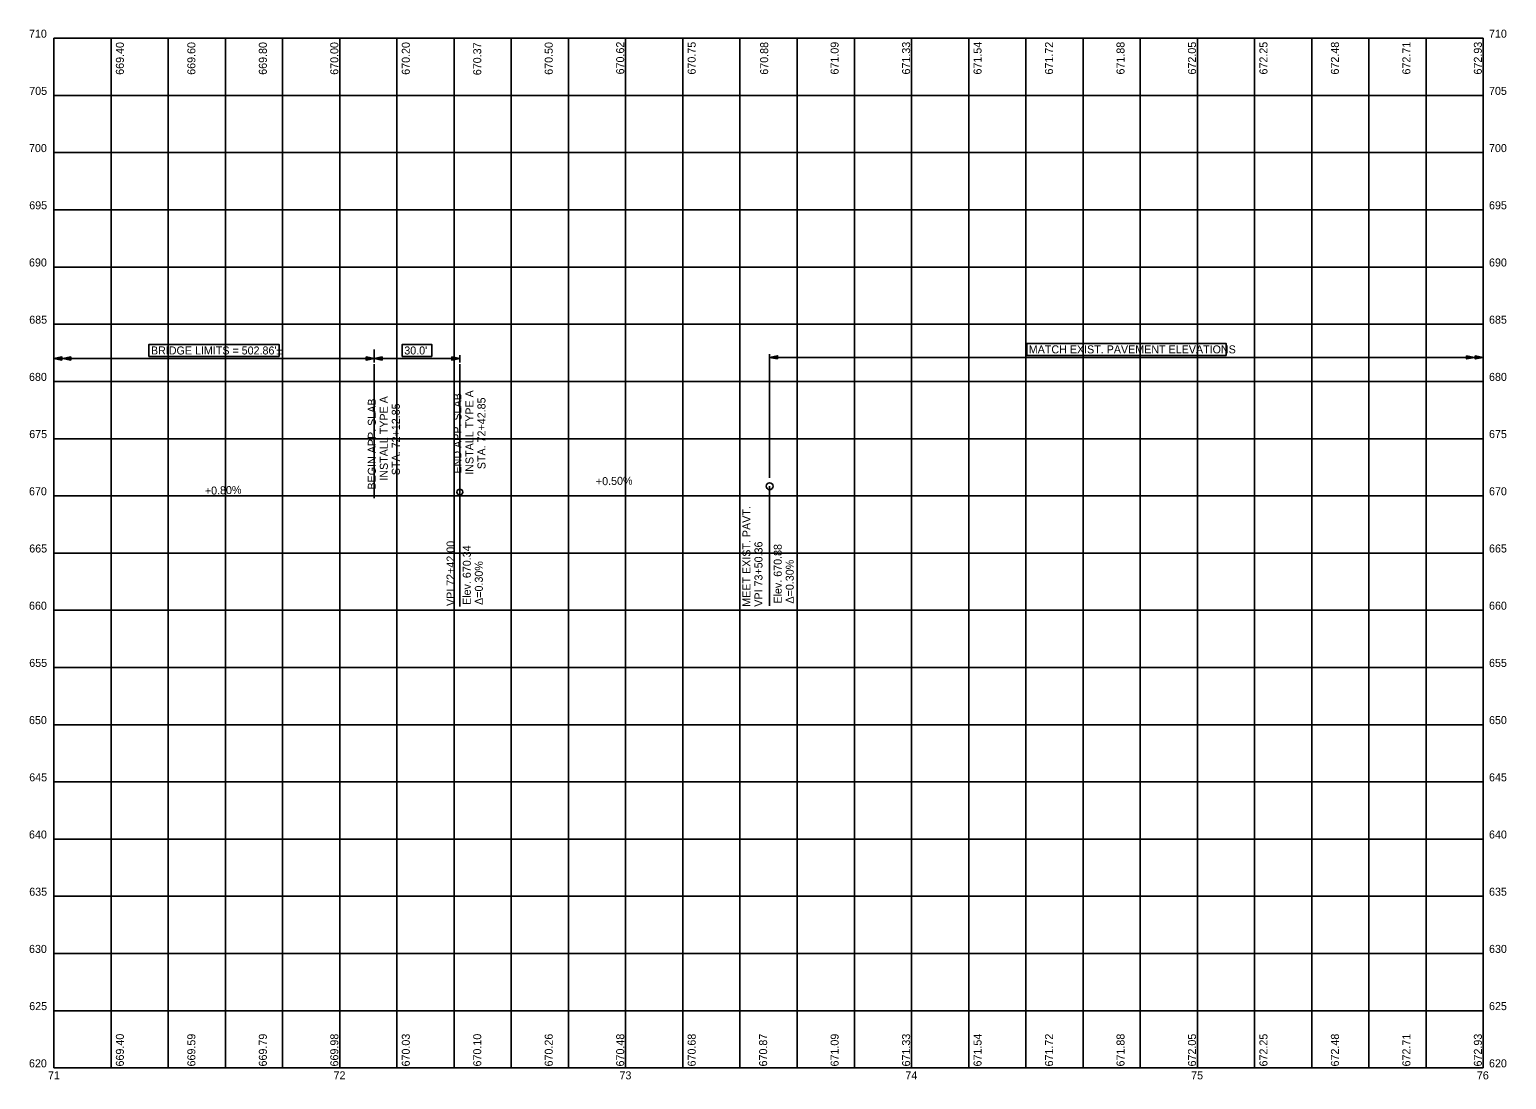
# Model space of a CAD drawing. Extents: x 1498 to 2015, y 616 to 983.
import ezdxf

# ---------------------------------------------------------------- set-up
doc = ezdxf.new("R2010")
doc.units = 0
for name, color, linetype in [('PF_P_Sta_Elev_Text', 7, 'Continuous'), ('PF_P_Text', 7, 'Continuous'), ('PF_P_Text_Strip_Grades_20', 7, 'Continuous'), ('PF_X_Text_Strip_Grade', 7, 'Continuous'), ('SH_Major_Grid_Line', 7, 'Continuous'), ('SH_Text', 7, 'Continuous')]:
    doc.layers.add(name, color=color, linetype=linetype)

msp = doc.modelspace()

# ---------------------------------------------------------------- linework, layer by layer
at = {"layer": 'PF_P_Text'}
for p, q in [((1757.33, 823.38), (1757.33, 781.5)), ((1648.97, 821.34), (1648.97, 781.33))]:
    msp.add_line(p, q, dxfattribs=at)
for centre, radius in [((1648.97, 821.34), 1.02), ((1757.33, 823.38), 1.2)]:
    msp.add_circle(centre, radius, dxfattribs=at)
at = {"layer": 'SH_Major_Grid_Line'}
for p, q in [((1506.97, 980), (2006.97, 980)), ((1506.97, 620), (1506.97, 980)), ((1506.97, 620), (1506.97, 980)), ((1526.97, 620), (1526.97, 980)), ((1546.97, 620), (1546.97, 980)), ((1566.97, 620), (1566.97, 980)), ((1586.97, 620), (1586.97, 980)), ((1606.97, 620), (1606.97, 980)), ((1626.97, 620), (1626.97, 980)), ((1646.97, 620), (1646.97, 980)), ((1666.97, 620), (1666.97, 980)), ((1686.97, 620), (1686.97, 980)), ((1706.97, 620), (1706.97, 980)), ((1726.97, 620), (1726.97, 980)), ((1746.97, 620), (1746.97, 980)), ((1766.97, 620), (1766.97, 980)), ((1786.97, 620), (1786.97, 980)), ((1806.97, 620), (1806.97, 980)), ((1826.97, 620), (1826.97, 980)), ((1846.97, 620), (1846.97, 980)), ((1866.97, 620), (1866.97, 980)), ((1886.97, 620), (1886.97, 980)), ((1906.97, 620), (1906.97, 980)), ((1926.97, 620), (1926.97, 980)), ((1946.97, 620), (1946.97, 980)), ((1966.97, 620), (1966.97, 980)), ((1986.97, 620), (1986.97, 980)), ((2006.97, 620), (2006.97, 980)), ((1506.97, 960), (2006.97, 960)), ((1506.97, 940), (2006.97, 940)), ((1506.97, 920), (2006.97, 920)), ((1506.97, 900), (2006.97, 900)), ((1506.97, 880), (2006.97, 880)), ((1506.97, 860), (2006.97, 860)), ((1506.97, 840), (2006.97, 840)), ((1506.97, 820), (2006.97, 820)), ((1506.97, 800), (2006.97, 800)), ((1506.97, 780), (2006.97, 780)), ((1506.97, 760), (2006.97, 760)), ((1506.97, 740), (2006.97, 740)), ((1506.97, 720), (2006.97, 720)), ((1506.97, 700), (2006.97, 700)), ((1506.97, 680), (2006.97, 680)), ((1506.97, 660), (2006.97, 660)), ((1506.97, 640), (2006.97, 640)), ((1506.97, 620), (2006.97, 620))]:
    msp.add_line(p, q, dxfattribs=at)
at = {"layer": 'SH_Text'}
for p, q in [((1506.97, 871.13), (1506.97, 866.64)), ((1619.01, 868.04), (1506.97, 868.04)), ((1619.01, 871.13), (1619.01, 866.64)), ((1619.01, 871.13), (1619.01, 866.64)), ((1619.01, 868.04), (1648.97, 868.04)), ((1648.97, 869.17), (1648.97, 866.64)), ((1757.33, 869.53), (1757.33, 826.32)), ((1757.33, 868.42), (2006.97, 868.42)), ((2006.97, 869.53), (2006.97, 867.02)), ((1619.01, 819.17), (1619.01, 866.08)), ((1648.97, 821.24), (1648.97, 866.1))]:
    msp.add_line(p, q, dxfattribs=at)
for points in [[(1847.29, 869.12), (1917.01, 869.12), (1917.01, 873.32), (1847.29, 873.32)], [(1509.77, 867.48), (1506.97, 868.04), (1509.77, 868.6)], [(1512.89, 867.48), (1510.09, 868.04), (1512.89, 868.6)], [(1540.24, 868.74), (1585.74, 868.74), (1585.74, 872.94), (1540.24, 872.94)], [(1616.21, 868.6), (1619.01, 868.04), (1616.21, 867.48)], [(1621.81, 867.48), (1619.01, 868.04), (1621.81, 868.6)], [(1628.85, 868.74), (1639.13, 868.74), (1639.13, 872.94), (1628.85, 872.94)], [(1646.17, 868.6), (1648.97, 868.04), (1646.17, 867.48)], [(1760.13, 867.86), (1757.33, 868.42), (1760.13, 868.98)], [(2001.1, 868.98), (2003.9, 868.42), (2001.1, 867.86)], [(2004.17, 868.98), (2006.97, 868.42), (2004.17, 867.86)]]:
    msp.add_lwpolyline(points, close=True, dxfattribs=at)

# ---------------------------------------------------------------- texts
at = {"layer": 'PF_P_Sta_Elev_Text'}
for s, p in [('710', (1498.28, 980.2)), ('710', (2008.97, 980.2)), ('705', (1498.36, 960.2)), ('705', (2008.97, 960.2)), ('700', (1498.28, 940.2)), ('700', (2008.97, 940.2)), ('695', (1498.36, 920.2)), ('695', (2008.97, 920.2)), ('690', (1498.28, 900.2)), ('690', (2008.97, 900.2)), ('685', (1498.36, 880.2)), ('685', (2008.97, 880.2)), ('680', (1498.28, 860.2)), ('680', (2008.97, 860.2)), ('675', (1498.36, 840.2)), ('675', (2008.97, 840.2)), ('670', (1498.28, 820.2)), ('670', (2008.97, 820.2)), ('665', (1498.36, 800.2)), ('665', (2008.97, 800.2)), ('660', (1498.28, 780.2)), ('660', (2008.97, 780.2)), ('655', (1498.36, 760.2)), ('655', (2008.97, 760.2)), ('650', (1498.28, 740.2)), ('650', (2008.97, 740.2)), ('645', (1498.36, 720.2)), ('645', (2008.97, 720.2)), ('640', (1498.28, 700.2)), ('640', (2008.97, 700.2)), ('635', (1498.36, 680.2)), ('635', (2008.97, 680.2)), ('630', (1498.28, 660.2)), ('630', (2008.97, 660.2)), ('625', (1498.36, 640.2)), ('625', (2008.97, 640.2)), ('620', (1498.28, 620.2)), ('620', (2008.97, 620.2)), ('71', (1504.94, 616)), ('72', (1604.81, 616)), ('73', (1704.82, 616)), ('74', (1804.82, 616)), ('75', (1904.78, 616)), ('76', (2004.73, 616))]:
    msp.add_text(s, height=2.8, dxfattribs=at).set_placement(p)
at = {"layer": 'PF_P_Text'}
for s, rotation, p in [('BEGIN APP. SLAB', 90, (1619.59, 822.21)), ('INSTALL TYPE A', 90, (1623.79, 825.31)), ('END APP. SLAB', 90, (1649.55, 827.81)), ('INSTALL TYPE A', 90, (1653.75, 827.38)), ('STA. 72+42.85', 90, (1657.95, 829.32)), ('STA. 72+12.85', 90, (1627.99, 827.25)), ('+0.50%', 1.1444, (1696.6, 823.69)), ('+0.80%', 1.8328, (1559.84, 820.36)), ('MEET EXIST. PAVT.', 90, (1750.64, 781.24)), ('VPI 72+42.00', 90, (1647.13, 781.48)), ('Elev. 670.34', 90, (1652.82, 781.87)), ('VPI 73+50.36', 90, (1754.84, 781.24)), ('Elev. 670.88', 90, (1761.57, 782.35)), ('Δ=0.30%', 90, (1657.02, 781.87)), ('Δ=0.30%', 90, (1765.77, 782.35))]:
    msp.add_text(s, height=2.8, rotation=rotation, dxfattribs=at).set_placement(p)
at = {"layer": 'PF_P_Text_Strip_Grades_20'}
for s, p in [('669.40', (1531.47, 967.22)), ('669.60', (1556.47, 967.22)), ('669.80', (1581.47, 967.22)), ('670.00', (1606.47, 967.22)), ('670.20', (1631.47, 967.22)), ('670.37', (1656.47, 967.08)), ('670.50', (1681.47, 967.22)), ('670.62', (1706.47, 967.36)), ('670.75', (1731.47, 967.31)), ('670.88', (1756.83, 967.25))]:
    msp.add_text(s, height=2.8, rotation=90, dxfattribs=at).set_placement(p)
at = {"layer": 'PF_X_Text_Strip_Grade'}
for s, p in [('671.09', (1781.47, 967.32)), ('671.33', (1806.47, 967.32)), ('671.54', (1831.47, 967.32)), ('671.72', (1856.47, 967.32)), ('671.88', (1881.47, 967.32)), ('672.05', (1906.47, 967.32)), ('672.25', (1931.47, 967.32)), ('672.48', (1956.47, 967.32)), ('672.71', (1981.47, 967.32)), ('672.93', (2006.47, 967.32)), ('669.40', (1531.47, 620.5)), ('669.59', (1556.47, 620.5)), ('669.79', (1581.47, 620.5)), ('669.98', (1606.47, 620.5)), ('670.03', (1631.47, 620.5)), ('670.10', (1656.47, 620.5)), ('670.26', (1681.47, 620.5)), ('670.48', (1706.47, 620.5)), ('670.68', (1731.47, 620.5)), ('670.87', (1756.47, 620.5)), ('671.09', (1781.47, 620.5)), ('671.33', (1806.47, 620.5)), ('671.54', (1831.47, 620.5)), ('671.72', (1856.47, 620.5)), ('671.88', (1881.47, 620.5)), ('672.05', (1906.47, 620.5)), ('672.25', (1931.47, 620.5)), ('672.48', (1956.47, 620.5)), ('672.71', (1981.47, 620.5)), ('672.93', (2006.47, 620.5))]:
    msp.add_text(s, height=2.8, rotation=90, dxfattribs=at).set_placement(p)
at = {"layer": 'SH_Text'}
for s, p in [("BRIDGE LIMITS = 502.86'±", (1540.94, 869.44)), ("30.0'", (1629.55, 869.44)), ('MATCH EXIST. PAVEMENT ELEVATIONS', (1847.99, 869.82))]:
    msp.add_text(s, height=2.8, dxfattribs=at).set_placement(p)

doc.saveas('drawing.dxf')
